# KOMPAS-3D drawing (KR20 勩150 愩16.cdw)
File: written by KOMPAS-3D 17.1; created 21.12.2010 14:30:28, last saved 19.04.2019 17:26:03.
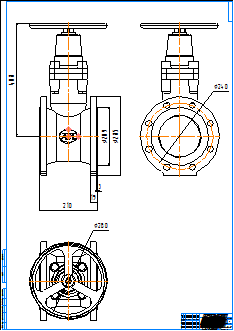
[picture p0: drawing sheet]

Title block, sheet 1: name: KR20 Ду150 Ру16; material: Внимание! Данный продукт является объектом авторского права ООО «Торговый Дом АДЛ». / Запрещается изменение, копирование, распространение / (в том числе путем копирования на другие сайты и ресурсы в Интернете) / или любое иное использование информации и объектов без предварительного / согласия правообладателя (ООО «Торговый Дом АДЛ»).; scale: 1:1; sheets: 1; organisation: ООО "Торговый дом АДЛ"; sheet format: A0; stored path: \\adlc.lan\data\АДЛ_ПКД\3D-модели\ADL production\Клиновые задвижки серии KR ГРАНАР\Клиновые задвижки KR20\KOMPAS 2D\KR20 Ду150 Ру16.cdw

Views: Спереди 1, Проекционный вид 2, Проекционный вид 3
Dimensions and other numbers on the sheet: 3; 19; 210; 209; 285; 408; 240; 280; 1:1; 1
